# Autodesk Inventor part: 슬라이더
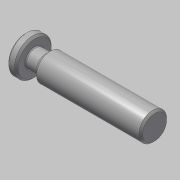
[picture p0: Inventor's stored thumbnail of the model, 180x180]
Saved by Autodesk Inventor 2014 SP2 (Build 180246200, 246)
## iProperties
Created: 2016-05
Part Number: 슬라이더
Document SubType Name: Modeling
Designer: mduedu
Density: 7.86 g/cm^3
Material: 강철, 연강
Appearance: 강철
Author: mduedu
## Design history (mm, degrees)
sketch "스케치1"
  geometry: L1 (-7.5, 0)-(62.5, 0); L2 (62.5, 0)-(62.5, 7.5); L3 (62.5, 7.5)-(0, 7.5); L4 (-7.5, 0)-(-7.5, 10); L5 (-7.5, 10)-(-2.5, 10); L6 (-2.5, 10)-(-2.5, 5); L7 (-2.5, 5)-(3.5, 5); L8 (3.5, 5)-(6, 7.5); A1 r 7.5 centre (0, 0) between (0, 7.5) and (-7.5, 0); 1 further point
  constraints: 16 end point, 3 perpendicular, 2 horizontal, 2 parallel, 2 point on circle, 2 point on line, 2 tangent, 1 centre point, 1 coincident
  dimensions: "d0" = 15 diameter of A1; "d1" = 70 distance of L1.start L1.end; "d19" = 20 diameter of L5 L1; "d20" = 10 diameter of L7 L1; "d21" = 5 distance of L4.end L5.end; "d22" = 135 deg angle of L8 L7; "d23" = 6 distance of L6.end L7.end
revolve "회전1" stored, may be unused: angle "d4" = 90 deg
chamfer "모따기2" distance "d24" = 1; stored, may be unused: second distance "d25" = 2, angle "d26" = 45 deg
fillet "모깎기1" dims "d27" = 0.5
node "솔리드1"
